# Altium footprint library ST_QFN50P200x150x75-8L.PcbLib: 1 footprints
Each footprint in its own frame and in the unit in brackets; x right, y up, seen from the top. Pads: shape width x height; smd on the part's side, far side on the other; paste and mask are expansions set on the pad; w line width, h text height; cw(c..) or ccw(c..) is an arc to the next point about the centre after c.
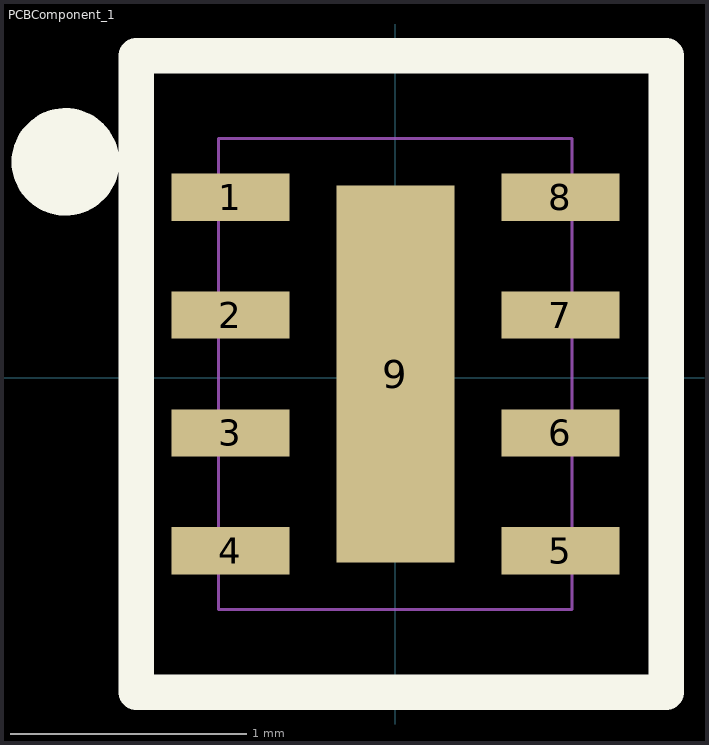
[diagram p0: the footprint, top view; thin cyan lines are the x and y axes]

## PCBComponent_1 [mm]
pads (9):
  rect 0.5x0.2 smd paste-20 mask+0.025: 1(-0.699,0.766) 2(-0.699,0.266) 3(-0.699,-0.234) 4(-0.699,-0.734) 5(0.701,-0.734) 6(0.701,-0.234) 7(0.701,0.266) 8(0.701,0.766)
  rect 0.5x1.6 smd paste-20 mask+0.025: 9(0.001,0.016)
Top Overlay:
  circle w0.254: c-1.399,0.916 r0.101
  lines w0.15: -1.099,-1.334 1.151,-1.334 1.151,1.366 -1.099,1.366 -1.099,-1.334
Top Paste:
  rectangle: -0.936,0.671 -0.462,0.861
  rectangle: -0.936,0.171 -0.462,0.361
  rectangle: -0.936,-0.329 -0.462,-0.139
  rectangle: -0.936,-0.829 -0.462,-0.639
  rectangle: 0.464,0.671 0.938,0.861
  rectangle: 0.464,0.171 0.938,0.361
  rectangle: 0.464,-0.329 0.938,-0.139
  rectangle: 0.464,-0.829 0.938,-0.639
  rectangle: -0.176,-0.55 0.178,0.581
Mechanical 9:
  lines w0.013: -0.749,-0.984 -0.749,1.016 ; -0.749,-0.984 0.751,-0.984 ; -0.749,-0.984 -0.749,1.016 ; -0.749,-0.984 0.751,-0.984 ; -0.749,1.016 0.751,1.016 ; -0.749,1.016 0.751,1.016 ; 0.751,-0.984 0.751,1.016 ; 0.751,-0.984 0.751,1.016
3D body "ST_QFN_2x1-5_w_logo.stp": height 0.82, standoff 0.01, extent -0.749,-0.984 0.751,1.016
